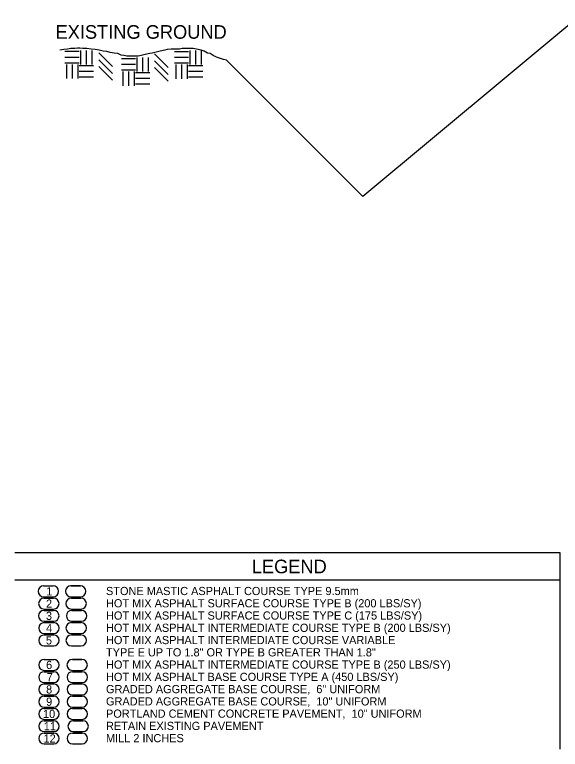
# Model space of a CAD drawing. Extents: x 2003207 to 2014043, y 843846 to 860154.
# Drawn here: x 2013805.7 to 2013845.7, y 844446 to 844499.9 of the extents above; entities that cross this region are included whole.
import ezdxf

# ---------------------------------------------------------------- set-up
doc = ezdxf.new("R2010")
doc.units = 0
for name, color, linetype in [('RD_EX_Road', 7, 'Continuous'), ('RD_EX_Road_txCode', 7, 'Continuous'), ('RD_QTY_ConcPave', 7, 'Continuous'), ('RD_QTY_Intermediate', 7, 'Continuous'), ('RD_QTY_Milling', 7, 'Continuous'), ('RD_QTY_Surf_Course', 7, 'Continuous'), ('RD_SHT_Bndy', 7, 'Continuous'), ('RD_TX_Misc2', 7, 'Continuous'), ('RD_TX_TypSect', 7, 'Continuous'), ('RD_XS_ExGround', 7, 'Continuous')]:
    doc.layers.add(name, color=color, linetype=linetype)

msp = doc.modelspace()

# ---------------------------------------------------------------- linework, layer by layer
at = {"layer": 'RD_EX_Road'}
for p, q in [((2013810.723, 844448.087), (2013810.023, 844448.087)), ((2013810.023, 844447.287), (2013810.723, 844447.287)), ((2013810.661, 844447.187), (2013809.961, 844447.187)), ((2013809.961, 844446.387), (2013810.661, 844446.387))]:
    msp.add_line(p, q, dxfattribs=at)
for centre, start, end in [((2013810.023, 844447.687), 90, 270), ((2013810.723, 844447.687), 270, 90), ((2013809.961, 844446.787), 90, 270), ((2013810.661, 844446.787), 270, 90)]:
    msp.add_arc(centre, 0.4, start, end, dxfattribs=at)
at = {"layer": 'RD_QTY_ConcPave'}
for p, q in [((2013810.661, 844450.787), (2013809.961, 844450.787)), ((2013809.961, 844449.987), (2013810.661, 844449.987)), ((2013810.661, 844449.887), (2013809.961, 844449.887)), ((2013809.961, 844449.087), (2013810.661, 844449.087)), ((2013810.661, 844448.987), (2013809.961, 844448.987)), ((2013809.961, 844448.187), (2013810.661, 844448.187))]:
    msp.add_line(p, q, dxfattribs=at)
for centre, start, end in [((2013809.961, 844450.387), 90, 270), ((2013810.661, 844450.387), 270, 90), ((2013809.961, 844449.487), 90, 270), ((2013810.661, 844449.487), 270, 90), ((2013809.961, 844448.587), 90, 270), ((2013810.661, 844448.587), 270, 90)]:
    msp.add_arc(centre, 0.4, start, end, dxfattribs=at)
at = {"layer": 'RD_QTY_Intermediate'}
for p, q in [((2013810.582, 844455.287), (2013809.882, 844455.287)), ((2013809.882, 844454.487), (2013810.582, 844454.487)), ((2013810.582, 844454.387), (2013809.882, 844454.387)), ((2013809.882, 844453.587), (2013810.582, 844453.587)), ((2013810.65, 844452.587), (2013809.95, 844452.587)), ((2013809.95, 844451.787), (2013810.65, 844451.787)), ((2013810.661, 844451.687), (2013809.961, 844451.687)), ((2013809.961, 844450.887), (2013810.661, 844450.887))]:
    msp.add_line(p, q, dxfattribs=at)
for centre, start, end in [((2013809.882, 844454.887), 90, 270), ((2013810.582, 844454.887), 270, 90), ((2013809.882, 844453.987), 90, 270), ((2013810.582, 844453.987), 270, 90), ((2013809.95, 844452.187), 90, 270), ((2013810.65, 844452.187), 270, 90), ((2013809.961, 844451.287), 90, 270), ((2013810.661, 844451.287), 270, 90)]:
    msp.add_arc(centre, 0.4, start, end, dxfattribs=at)
at = {"layer": 'RD_QTY_Milling'}
for p, q in [((2013810.661, 844447.187), (2013809.961, 844447.187)), ((2013809.961, 844446.387), (2013810.661, 844446.387))]:
    msp.add_line(p, q, dxfattribs=at)
for centre, start, end in [((2013809.961, 844446.787), 90, 270), ((2013810.661, 844446.787), 270, 90)]:
    msp.add_arc(centre, 0.4, start, end, dxfattribs=at)
at = {"layer": 'RD_QTY_Surf_Course'}
for p, q in [((2013810.542, 844457.987), (2013809.842, 844457.987)), ((2013809.842, 844457.187), (2013810.542, 844457.187)), ((2013810.576, 844457.087), (2013809.876, 844457.087)), ((2013809.876, 844456.287), (2013810.576, 844456.287)), ((2013810.61, 844456.187), (2013809.91, 844456.187)), ((2013809.91, 844455.387), (2013810.61, 844455.387))]:
    msp.add_line(p, q, dxfattribs=at)
for centre, start, end in [((2013809.842, 844457.587), 90, 270), ((2013810.542, 844457.587), 270, 90), ((2013809.876, 844456.687), 90, 270), ((2013810.576, 844456.687), 270, 90), ((2013809.91, 844455.787), 90, 270), ((2013810.61, 844455.787), 270, 90)]:
    msp.add_arc(centre, 0.4, start, end, dxfattribs=at)
at = {"layer": 'RD_SHT_Bndy'}
for p, q in [((2013845.721, 844460.41), (2013805.721, 844460.41)), ((2013845.721, 844458.41), (2013845.721, 844460.41)), ((2013845.721, 844458.41), (2013805.721, 844458.41)), ((2013845.721, 844445.992), (2013845.721, 844458.41))]:
    msp.add_line(p, q, dxfattribs=at)
at = {"layer": 'RD_TX_Misc2'}
for p, q in [((2013807.842, 844457.987), (2013808.542, 844457.987)), ((2013809.842, 844457.987), (2013810.542, 844457.987)), ((2013807.842, 844457.187), (2013808.542, 844457.187)), ((2013807.876, 844457.087), (2013808.576, 844457.087)), ((2013809.842, 844457.187), (2013810.542, 844457.187)), ((2013809.876, 844457.087), (2013810.576, 844457.087)), ((2013807.871, 844456.187), (2013808.571, 844456.187)), ((2013807.876, 844456.287), (2013808.576, 844456.287)), ((2013809.876, 844456.287), (2013810.576, 844456.287)), ((2013809.91, 844456.187), (2013810.61, 844456.187)), ((2013807.871, 844455.387), (2013808.571, 844455.387)), ((2013809.91, 844455.387), (2013810.61, 844455.387)), ((2013807.882, 844455.287), (2013808.582, 844455.287)), ((2013809.882, 844455.287), (2013810.582, 844455.287)), ((2013807.882, 844454.487), (2013808.582, 844454.487)), ((2013807.882, 844454.387), (2013808.582, 844454.387)), ((2013809.882, 844454.487), (2013810.582, 844454.487)), ((2013809.882, 844454.387), (2013810.582, 844454.387)), ((2013807.882, 844453.587), (2013808.582, 844453.587)), ((2013809.882, 844453.587), (2013810.582, 844453.587)), ((2013807.882, 844452.587), (2013808.582, 844452.587)), ((2013809.95, 844452.587), (2013810.65, 844452.587)), ((2013807.882, 844451.787), (2013808.582, 844451.787)), ((2013807.882, 844451.687), (2013808.582, 844451.687)), ((2013809.95, 844451.787), (2013810.65, 844451.787)), ((2013809.961, 844451.687), (2013810.661, 844451.687)), ((2013807.882, 844450.887), (2013808.582, 844450.887)), ((2013807.882, 844450.787), (2013808.582, 844450.787)), ((2013809.961, 844450.887), (2013810.661, 844450.887)), ((2013809.961, 844450.787), (2013810.661, 844450.787)), ((2013807.882, 844449.987), (2013808.582, 844449.987)), ((2013809.961, 844449.987), (2013810.661, 844449.987)), ((2013807.882, 844449.887), (2013808.582, 844449.887)), ((2013809.961, 844449.887), (2013810.661, 844449.887)), ((2013807.882, 844449.087), (2013808.582, 844449.087)), ((2013807.882, 844448.987), (2013808.582, 844448.987)), ((2013809.961, 844449.087), (2013810.661, 844449.087)), ((2013809.961, 844448.987), (2013810.661, 844448.987)), ((2013807.882, 844448.187), (2013808.582, 844448.187)), ((2013807.882, 844448.087), (2013808.582, 844448.087)), ((2013809.961, 844448.187), (2013810.661, 844448.187)), ((2013810.023, 844448.087), (2013810.723, 844448.087)), ((2013807.882, 844447.287), (2013808.582, 844447.287)), ((2013810.023, 844447.287), (2013810.723, 844447.287)), ((2013807.882, 844447.187), (2013808.582, 844447.187)), ((2013809.961, 844447.187), (2013810.661, 844447.187)), ((2013807.882, 844446.387), (2013808.582, 844446.387)), ((2013809.961, 844446.387), (2013810.661, 844446.387))]:
    msp.add_line(p, q, dxfattribs=at)
for centre, start, end in [((2013807.842, 844457.587), 90, 270), ((2013808.542, 844457.587), 270, 90), ((2013809.842, 844457.587), 90, 270), ((2013810.542, 844457.587), 270, 90), ((2013807.876, 844456.687), 90, 270), ((2013808.576, 844456.687), 270, 90), ((2013809.876, 844456.687), 90, 270), ((2013810.576, 844456.687), 270, 90), ((2013807.871, 844455.787), 90, 270), ((2013808.571, 844455.787), 270, 90), ((2013809.91, 844455.787), 90, 270), ((2013810.61, 844455.787), 270, 90), ((2013807.882, 844454.887), 90, 270), ((2013808.582, 844454.887), 270, 90), ((2013809.882, 844454.887), 90, 270), ((2013810.582, 844454.887), 270, 90), ((2013807.882, 844453.987), 90, 270), ((2013808.582, 844453.987), 270, 90), ((2013809.882, 844453.987), 90, 270), ((2013810.582, 844453.987), 270, 90), ((2013807.882, 844452.187), 90, 270), ((2013808.582, 844452.187), 270, 90), ((2013809.95, 844452.187), 90, 270), ((2013810.65, 844452.187), 270, 90), ((2013807.882, 844451.287), 90, 270), ((2013808.582, 844451.287), 270, 90), ((2013809.961, 844451.287), 90, 270), ((2013810.661, 844451.287), 270, 90), ((2013807.882, 844450.387), 90, 270), ((2013808.582, 844450.387), 270, 90), ((2013809.961, 844450.387), 90, 270), ((2013810.661, 844450.387), 270, 90), ((2013807.882, 844449.487), 90, 270), ((2013808.582, 844449.487), 270, 90), ((2013809.961, 844449.487), 90, 270), ((2013810.661, 844449.487), 270, 90), ((2013807.882, 844448.587), 90, 270), ((2013808.582, 844448.587), 270, 90), ((2013809.961, 844448.587), 90, 270), ((2013810.661, 844448.587), 270, 90), ((2013807.882, 844447.687), 90, 270), ((2013808.582, 844447.687), 270, 90), ((2013810.023, 844447.687), 90, 270), ((2013810.723, 844447.687), 270, 90), ((2013807.882, 844446.787), 90, 270), ((2013808.582, 844446.787), 270, 90), ((2013809.961, 844446.787), 90, 270), ((2013810.661, 844446.787), 270, 90)]:
    msp.add_arc(centre, 0.4, start, end, dxfattribs=at)
at = {"layer": 'RD_XS_ExGround'}
for p, q in [((2013847.261, 844499.905), (2013831.261, 844486.572)), ((2013810.448, 844497.192), (2013809.407, 844497.192)), ((2013810.545, 844497.289), (2013810.545, 844496.247)), ((2013810.962, 844497.289), (2013810.962, 844496.247)), ((2013811.378, 844497.289), (2013811.378, 844496.247)), ((2013812.901, 844496.098), (2013811.901, 844497.098)), ((2013816.969, 844496.025), (2013815.969, 844497.025)), ((2013818.475, 844497.187), (2013817.434, 844497.187)), ((2013818.572, 844497.284), (2013818.572, 844496.242)), ((2013818.988, 844497.284), (2013818.988, 844496.242)), ((2013819.405, 844497.284), (2013819.405, 844496.242)), ((2013810.448, 844496.775), (2013809.407, 844496.775)), ((2013810.448, 844496.359), (2013809.407, 844496.359)), ((2013812.901, 844495.598), (2013811.901, 844496.598)), ((2013814.585, 844496.673), (2013813.543, 844496.673)), ((2013814.681, 844496.77), (2013814.681, 844495.729)), ((2013815.098, 844496.77), (2013815.098, 844495.729)), ((2013815.514, 844496.77), (2013815.514, 844495.729)), ((2013816.969, 844495.525), (2013815.969, 844496.525)), ((2013818.475, 844496.77), (2013817.434, 844496.77)), ((2013818.475, 844496.354), (2013817.434, 844496.354)), ((2013831.261, 844486.572), (2013821.261, 844496.572)), ((2013809.511, 844496.254), (2013809.511, 844495.213)), ((2013809.928, 844496.254), (2013809.928, 844495.213)), ((2013810.344, 844496.254), (2013810.344, 844495.213)), ((2013811.49, 844496.15), (2013810.448, 844496.15)), ((2013812.901, 844495.098), (2013811.901, 844496.098)), ((2013814.585, 844496.257), (2013813.543, 844496.257)), ((2013814.585, 844495.84), (2013813.543, 844495.84)), ((2013816.969, 844495.025), (2013815.969, 844496.025)), ((2013817.538, 844496.25), (2013817.538, 844495.208)), ((2013817.954, 844496.25), (2013817.954, 844495.208)), ((2013818.371, 844496.25), (2013818.371, 844495.208)), ((2013819.517, 844496.145), (2013818.475, 844496.145)), ((2013811.49, 844495.734), (2013810.448, 844495.734)), ((2013811.49, 844495.317), (2013810.448, 844495.317)), ((2013813.647, 844495.736), (2013813.647, 844494.694)), ((2013814.064, 844495.736), (2013814.064, 844494.694)), ((2013814.481, 844495.736), (2013814.481, 844494.694)), ((2013815.626, 844495.632), (2013814.585, 844495.632)), ((2013819.517, 844495.729), (2013818.475, 844495.729)), ((2013819.517, 844495.312), (2013818.475, 844495.312)), ((2013815.626, 844495.215), (2013814.585, 844495.215)), ((2013815.626, 844494.798), (2013814.585, 844494.798))]:
    msp.add_line(p, q, dxfattribs=at)
msp.add_lwpolyline([(2013821.261, 844496.572), (2013821.041, 844496.608), (2013820.822, 844496.682), (2013820.529, 844496.792), (2013820.273, 844496.901), (2013820.053, 844497.048), (2013819.87, 844497.085), (2013819.614, 844497.231), (2013819.394, 844497.304), (2013819.065, 844497.378), (2013818.808, 844497.414), (2013818.516, 844497.414), (2013818.186, 844497.414), (2013818.003, 844497.414), (2013817.82, 844497.378), (2013817.6, 844497.378), (2013817.381, 844497.378), (2013817.198, 844497.378), (2013816.905, 844497.341), (2013816.722, 844497.304), (2013816.393, 844497.231), (2013816.1, 844497.158), (2013815.807, 844497.085), (2013815.624, 844497.048), (2013815.294, 844496.975), (2013815.002, 844496.901), (2013814.782, 844496.865), (2013814.599, 844496.865), (2013814.379, 844496.865), (2013814.16, 844496.865), (2013813.94, 844496.865), (2013813.72, 844496.901), (2013813.537, 844496.938), (2013813.281, 844497.048), (2013813.025, 844497.085), (2013812.732, 844497.121), (2013812.476, 844497.194), (2013812.22, 844497.231), (2013811.927, 844497.304), (2013811.634, 844497.341), (2013811.341, 844497.378), (2013811.012, 844497.414), (2013810.719, 844497.414), (2013810.499, 844497.451), (2013810.316, 844497.451), (2013810.133, 844497.414), (2013809.84, 844497.414), (2013809.584, 844497.378), (2013809.328, 844497.341), (2013809.035, 844497.304)], dxfattribs=at)

# ---------------------------------------------------------------- texts
at = {"layer": 'RD_EX_Road_txCode'}
for s, height, p in [('LEGEND', 1, (2013823.11, 844458.91)), ('STONE MASTIC ASPHALT COURSE TYPE 9.5mm', 0.6, (2013812.417, 844457.31)), ('HOT MIX ASPHALT SURFACE COURSE TYPE B (200 LBS/SY)', 0.6, (2013812.417, 844456.41)), ('HOT MIX ASPHALT SURFACE COURSE TYPE C (175 LBS/SY)', 0.6, (2013812.417, 844455.51)), ('HOT MIX ASPHALT INTERMEDIATE COURSE TYPE B (200 LBS/SY)', 0.6, (2013812.417, 844454.61)), ('HOT MIX ASPHALT INTERMEDIATE COURSE VARIABLE ', 0.6, (2013812.417, 844453.71)), ('TYPE E UP TO 1.8" OR TYPE B GREATER THAN 1.8"', 0.6, (2013812.417, 844452.81)), ('HOT MIX ASPHALT INTERMEDIATE COURSE TYPE B (250 LBS/SY)', 0.6, (2013812.417, 844451.91)), ('HOT MIX ASPHALT BASE COURSE TYPE A (450 LBS/SY)', 0.6, (2013812.417, 844451.01)), ('GRADED AGGREGATE BASE COURSE,  6" UNIFORM', 0.6, (2013812.417, 844450.11)), ('GRADED AGGREGATE BASE COURSE,  10" UNIFORM', 0.6, (2013812.417, 844449.21)), ('PORTLAND CEMENT CONCRETE PAVEMENT,  10" UNIFORM', 0.6, (2013812.417, 844448.31)), ('RETAIN EXISTING PAVEMENT', 0.6, (2013812.417, 844447.41)), ('MILL 2 INCHES', 0.6, (2013812.417, 844446.51))]:
    msp.add_text(s, height=height, dxfattribs=at).set_placement(p)
at = {"layer": 'RD_TX_Misc2'}
for s, p in [('1', (2013808.039, 844457.287)), ('2', (2013808.022, 844456.387)), ('3', (2013808.011, 844455.487)), ('4', (2013808.023, 844454.587)), ('5', (2013808.011, 844453.687)), ('6', (2013808.023, 844451.887)), ('7 ', (2013808.066, 844450.987)), ('8', (2013808.023, 844450.087)), ('9', (2013808.023, 844449.187)), ('10', (2013807.796, 844448.287)), ('11', (2013807.852, 844447.387)), ('12', (2013807.835, 844446.487))]:
    msp.add_text(s, height=0.6, dxfattribs=at).set_placement(p)
at = {"layer": 'RD_TX_TypSect'}
msp.add_text('EXISTING GROUND', height=1, dxfattribs=at).set_placement((2013808.716, 844498.138))

doc.saveas('drawing.dxf')
